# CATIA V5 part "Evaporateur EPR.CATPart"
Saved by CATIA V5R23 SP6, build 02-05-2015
Part number: Evaporateur EPR
Publications: "CATRouFace1", "CATRouCenter1", "CATRouCircular1", "CATRouDatumPt1", "CATRouFace2", "CATRouCenter2", "CATRouCircular2", "CATRouDatumPt2"
Bounding box of the stored display mesh (mm): x -2399.862 to 2399.862, y -2399.862 to 2399.862, z -13077.592 to 9350
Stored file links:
  \\etu.ad.univ-lorraine.fr\bordron1\Documents\Parts EPR\Evaporateur EPR.CATPart
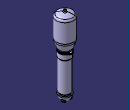
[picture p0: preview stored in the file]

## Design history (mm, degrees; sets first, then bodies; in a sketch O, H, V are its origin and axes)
AxisSystem1: origin (0, 0, 0), X (1, 0, 0), Y (0, 1, 0), Z (0, 0, 1)
Set1
  Point1: type OnSurface, Support face of Shaft1 from Sketch1.A2, Length 53.707, Direction (-0.292, -0.7517, -0.5913)
  Plane1: type Tangent, Support face of Shaft1 from Sketch1.A2, RefPoint Point1
  Point2: type Center, Curve edge [face of Pad3 from Sketch3.A1 | end face of Pad3]
  Point3: type Center, Curve edge [face of Mirror2 | face of Mirror2]
  Line1: type Normal, RefPoint Point2, RefSkin end face of Pad3, Start -659, End 101
  Point4: type OnCurve, Support edge [face of Pad3 from Sketch3.A1 | end face of Pad3], RefPoint {extremum Reference edge [face of Pad3 from Sketch3.A1 | end face of Pad3], Direction (1, 2, 3)}, Length 0
  Line2: type PtPt, FirstPoint Point4, SecondPoint Point2
  Plane2: type 2Lines, Element1 Line1, Element2 Line2
  Point5: type OnCurve, Support edge [face of Mirror2 | face of Mirror2], RefPoint {extremum Reference edge [face of Mirror2 | face of Mirror2], Direction (1, 2, 3)}, Length 0
  Line3: type PtPt, FirstPoint Point3, SecondPoint Point5
  Line4: type Normal, RefPoint Point3, RefSkin face of Mirror2, Start -659, End 101
  Plane3: type 2Lines, Element1 Line4, Element2 Line3
Body1 (main body)
  Sketch1 on YZ plane of AxisSystem1, origin (0, 0, 0), H (0, 1, 0), V (0, 0, 1)
    line L1 (-2400, 7840.9848) -> (-2400, 2517.422)
    point P1 (-2400, 8212.5577)
    reference projected line E1 through (0, 0) direction (0, 1) from edge [ZX plane of AxisSystem1 | YZ plane of AxisSystem1]
    line L2 (-1580, -176.327) -> (-1580, -300)
    point P2 (-1580, 0)
    line L3 (-2309.5389, 2004.3917) -> (-1640.3074, 165.6932)
    point P4 (-1580, 0)
    line L4 (-1580, -300) -> (-1680, -300)
    line L5 (-1680, -300) -> (-1680, -400)
    line L6 (-1680, -400) -> (-1580, -400)
    point P7 (-1580, -400)
    line L7 (-1580, -400) -> (-1580, -550)
    line L8 (-1580, -550) -> (-1680, -550)
    point P9 (-1680, -550)
    line L9 (-1680, -550) -> (-1680, -650)
    line L10 (-1680, -650) -> (-1580, -650)
    point P11 (-1580, -650)
    line L11 (-1580, -650) -> (-1580, -2100)
    line L12 (-1556.6044, -2164.2788) -> (-1523.3956, -2203.8556)
    line L13 (-1500, -2268.1343) -> (-1500, -10700)
    arc A1 centre (0, 5012.5577) radius 4000 from (-523.8095, 8978.1123) to (-2060.6061, 8440.9542) ccw
    point P13 (0, 5012.5577)
    point P14 (-2400, 8212.5577)
    point P15 (-350, 8997.2157)
    reference projected line E2 through (0, 0) direction (0, 1) from edge [ZX plane of AxisSystem1 | YZ plane of AxisSystem1]
    line L14 (-1500, -10700) -> (-1750, -10700)
    line L15 (-1750, -10700) -> (-1750, -11000)
    line L16 (-1750, -11000) -> (-1500, -11000)
    point P18 (-1500, -11000)
    line L17 (-1500, -11000) -> (-1500, -11500)
    arc A2 centre (0, -11500) radius 1500 from (-1500, -11500) to (0, -13000) ccw
    point P20 (0, -11500)
    point P21 (0, -13000)
    reference intersected line E3 through (0, 0) direction (0, 1) from ZX plane of AxisSystem1
    axis line L18 (-3420.8524, 0) -> (3131.5245, 0)
    reference projected line E4 through (0, 0) direction (1, 0) from edge [YZ plane of AxisSystem1 | XY plane of AxisSystem1]
    arc A3 centre (-1700, 7840.9848) radius 700 from (-2060.6061, 8440.9542) to (-2400, 7840.9848) ccw
    arc A4 centre (-900, 2517.422) radius 1500 from (-2400, 2517.422) to (-2309.5389, 2004.3917) ccw
    arc A5 centre (-2580, -176.327) radius 1000 from (-1640.3074, 165.6932) to (-1580, -176.327) cw
    arc A6 centre (-1480, -2100) radius 100 from (-1556.6044, -2164.2788) to (-1580, -2100) cw
    arc A7 centre (-1600, -2268.1343) radius 100 from (-1523.3956, -2203.8556) to (-1500, -2268.1343) cw
    line L19 (-350, 9350) -> (-350, 9176.39)
    point P40 (-350, 8997.2157)
    line L20 (-300, 9350) -> (-300, 8700)
    line L21 (-350, 9350) -> (-300, 9350)
    line L22 (-300, 8700) -> (0, 8700)
    point P43 (0, 8700)
    arc A8 centre (-550, 9176.39) radius 200 from (-523.8095, 8978.1123) to (-350, 9176.39) ccw
    distance L1 E1 = 2400
    radius A1 = 4000
    angle L3 E2 = 20
    distance P21 P15 = 22000
    length L17 = 500
    length L15 = 300
    distance L13 E3 = 1500
    distance L18 P21 = 13000
    length L10 = 100
    length L5 = 100
    length L9 = 100
    length L7 = 150
    distance L4 L18 = 300
    length L14 = 250
    radius A3 = 700
    radius A4 = 1500
    radius A5 = 1000
    distance L11 L13 = 80
    angle L12 L13 = 140
    radius A6 = 100
    radius A7 = 100
    length L11 = 1450
    length L22 = 300
    length L21 = 50
    distance L22 L18 = 8700
    length L20 = 650
    radius A8 = 200
    vertical: L1 V, L2 V, L5 V, L7 V, L9 V, L11 V, L13 V, L15 V, L17 V, L19 V, L20 V
    coincidence: P4 P2, P7 L2, P9 L5, P11 L2, P13 V, P14 L1, P14 P1, P18 L13, P20 V, P21 V, P2 L18, L18 E4, A1 P14, L1 P1, L3 P4, L2 P2, P40 P15, P43 V, A1 P15, L19 P40
    horizontal: L4 H, L6 H, L8 H, L10 H, L14 H, L16 H, L18 H, L21 H, L22 H
    tangency: A2 L13, A3 A1, A3 L1, A4 L1, A4 L3, A5 L3, A5 L2, A6 L12, A6 L11, A7 L12, A7 L13, A8 A1, A8 L19
  Shaft1: profile Sketch1, axis edge [ZX plane of AxisSystem1 | YZ plane of AxisSystem1], angle 360
  Sketch2 on XY plane of AxisSystem1, origin (0, 0, 0), H (1, 0, 0), V (0, 1, 0)
    projected circle E1 centre (0, 0) radius 1680 from edge [face of Shaft1 from Sketch1.L5 | face of Shaft1 from Sketch1.L4]
    projected arc E2 centre (0, 0) radius 1680 from (600, 1569.2036) to (-600, 1569.2036) ccw from edge [face of Shaft1 from Sketch1.L5 | face of Shaft1 from Sketch1.L4]
    line L1 (-600, 1569.2036) -> (-600, 1907.8784)
    point P1 (-600, 1569.2036)
    point P3 (600, 1907.8784)
    line L2 (600, 1907.8784) -> (600, 1569.2036)
    point P4 (600, 1569.2036)
    arc A1 centre (0, 0) radius 2000 from (600, 1907.8784) to (-600, 1907.8784) ccw
    point P5 (600, 1907.8784)
    reference projected line E3 through (0, 0) direction (0, 1) from edge [YZ plane of AxisSystem1 | XY plane of AxisSystem1]
    circle A2 centre (-392.7018, 1794.162) radius 75
    circle A3 centre (392.7018, 1794.162) radius 75
    distance L2 L1 = 1200
    radius A1 = 2000
    radius A2 = 75
    coincidence: P1 E1, P4 E1, P3 P5
    vertical: L1 V, L2 V
    symmetry: L1 L2 E3, A2 A3 V
  Pad1: profile Sketch2, direction (0, 0, 1), up to face of Shaft1 from Sketch1.L6, opposite side up to face of Shaft1 from Sketch1.L4
  Pad2: profile Sketch2, direction (0, 0, 1), up to face of Shaft1 from Sketch1.L10, opposite side up to face of Shaft1 from Sketch1.L8
  Mirror1: of Pad1, Sketch2, Pad2, Sketch2, about ZX plane of AxisSystem1
  Sketch3 on Plane1, origin (6024.7495, 3081.983, -7191.9023), H (0.4554, -0.8903, 0), V (0.6484, 0.3317, 0.6853)
    circle A1 centre (0, -7880.7317) radius 385
    point P1 (0, -7880.7317)
    reference projected point E1 (0, -7880.7317) from Point1
    circle A2 centre (0, -7880.7317) radius 442.5
    radius A1 = 385
    radius A2 = 442.5
    coincidence: P1 E1
  Pad3: profile Sketch3, direction (0.6101, 0.3121, -0.7283), length 250, opposite side length 200
  Fillet1: radius 200, on edge [face of Pad3 from Sketch3.A2 | face of Shaft1 from Sketch1.A2]
  Mirror2: of Pad3, Sketch3, Fillet1, about YZ plane of AxisSystem1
